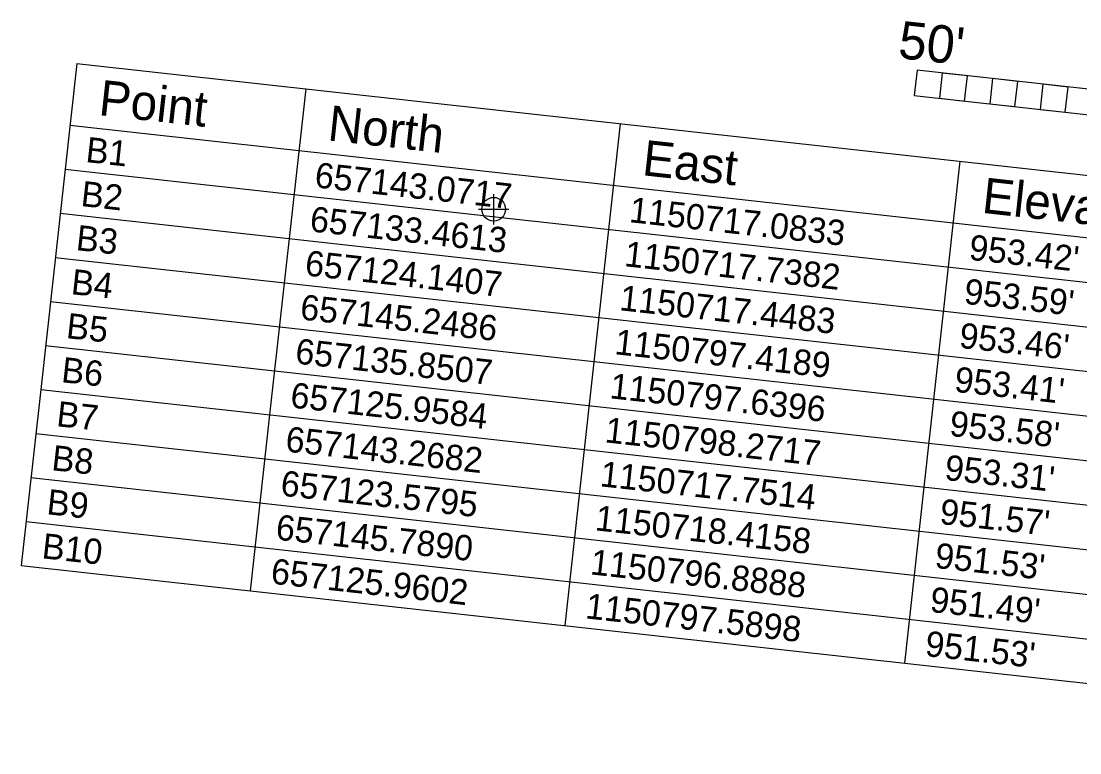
# Model space of a CAD drawing. Extents: x 1150279 to 1151282, y 654632 to 657999.
# Drawn here: x 1150700.1 to 1150909.2, y 656828.1 to 656972.6 of the extents above; entities that cross this region are included whole.
import ezdxf

# ---------------------------------------------------------------- set-up
doc = ezdxf.new("R2010")
doc.units = 0
for name, color, linetype in [('Cogo Default Point CELL', 7, 'Continuous'), ('CTL Sheet Datum Description CELL', 7, 'Continuous'), ('Exist Other Culture Located Object Text', 7, 'Continuous')]:
    doc.layers.add(name, color=color, linetype=linetype)

msp = doc.modelspace()

# ---------------------------------------------------------------- linework, layer by layer
at = {"layer": 'Cogo Default Point CELL'}
for points in [[(1150793.42, 656938.45), (1150793.42, 656935.45)], [(1150790.42, 656935.45), (1150793.42, 656935.45)], [(1150793.42, 656935.45), (1150796.42, 656935.45)], [(1150793.42, 656935.45), (1150793.42, 656932.45)]]:
    msp.add_lwpolyline(points, dxfattribs=at)
msp.add_circle((1150793.42, 656935.45), 2.34, dxfattribs=at)
at = {"layer": 'CTL Sheet Datum Description CELL'}
for points in [[(1150876.48, 656957.93), (1151025.57, 656941.43), (1151026.12, 656946.4), (1150877.03, 656962.9)], [(1150881.45, 656957.38), (1150886.42, 656956.83), (1150886.97, 656961.8), (1150882, 656962.35)], [(1150891.39, 656956.28), (1150896.36, 656955.73), (1150896.91, 656960.7), (1150891.94, 656961.25)], [(1150901.33, 656955.18), (1150906.3, 656954.63), (1150906.85, 656959.6), (1150901.88, 656960.15)]]:
    msp.add_lwpolyline(points, close=True, dxfattribs=at)
at = {"layer": 'Exist Other Culture Located Object Text'}
for p, q in [((1150711.08, 656964.22), (1150703.96, 656899.86)), ((1150711.08, 656964.22), (1151045.54, 656927.21)), ((1150756.3, 656959.21), (1150749.18, 656894.86)), ((1150709.73, 656952.04), (1151044.19, 656915.04)), ((1150818.42, 656952.34), (1150811.3, 656887.98)), ((1150885.51, 656944.92), (1150878.39, 656880.56)), ((1150708.77, 656943.34), (1151043.23, 656906.34)), ((1150708.77, 656943.34), (1151043.23, 656906.34)), ((1150708.77, 656943.34), (1151043.23, 656906.34)), ((1150708.77, 656943.34), (1151043.23, 656906.34)), ((1150708.77, 656943.34), (1151043.23, 656906.34)), ((1150707.8, 656934.65), (1151042.26, 656897.64)), ((1150707.8, 656934.65), (1151042.26, 656897.64)), ((1150707.8, 656934.65), (1151042.26, 656897.64)), ((1150707.8, 656934.65), (1151042.26, 656897.64)), ((1150707.8, 656934.65), (1151042.26, 656897.64)), ((1150706.84, 656925.95), (1151041.3, 656888.95)), ((1150706.84, 656925.95), (1151041.3, 656888.95)), ((1150706.84, 656925.95), (1151041.3, 656888.95)), ((1150706.84, 656925.95), (1151041.3, 656888.95)), ((1150706.84, 656925.95), (1151041.3, 656888.95)), ((1150705.88, 656917.25), (1151040.34, 656880.25)), ((1150705.88, 656917.25), (1151040.34, 656880.25)), ((1150705.88, 656917.25), (1151040.34, 656880.25)), ((1150705.88, 656917.25), (1151040.34, 656880.25)), ((1150705.88, 656917.25), (1151040.34, 656880.25)), ((1150704.92, 656908.56), (1151039.38, 656871.55)), ((1150704.92, 656908.56), (1151039.38, 656871.55)), ((1150704.92, 656908.56), (1151039.38, 656871.55)), ((1150704.92, 656908.56), (1151039.38, 656871.55)), ((1150704.92, 656908.56), (1151039.38, 656871.55)), ((1150703.96, 656899.86), (1150700.11, 656865.07)), ((1150703.96, 656899.86), (1151038.42, 656862.86)), ((1150703.96, 656899.86), (1151038.42, 656862.86)), ((1150703.96, 656899.86), (1151038.42, 656862.86)), ((1150703.96, 656899.86), (1151038.42, 656862.86)), ((1150703.96, 656899.86), (1151038.42, 656862.86)), ((1150749.18, 656894.86), (1150745.33, 656860.07)), ((1150702.99, 656891.16), (1151037.45, 656854.16)), ((1150702.99, 656891.16), (1151037.45, 656854.16)), ((1150702.99, 656891.16), (1151037.45, 656854.16)), ((1150702.99, 656891.16), (1151037.45, 656854.16)), ((1150702.99, 656891.16), (1151037.45, 656854.16)), ((1150811.3, 656887.98), (1150807.45, 656853.19)), ((1150702.03, 656882.46), (1151036.49, 656845.46)), ((1150702.03, 656882.46), (1151036.49, 656845.46)), ((1150702.03, 656882.46), (1151036.49, 656845.46)), ((1150702.03, 656882.46), (1151036.49, 656845.46)), ((1150702.03, 656882.46), (1151036.49, 656845.46)), ((1150878.39, 656880.56), (1150874.54, 656845.77)), ((1150701.07, 656873.77), (1151035.53, 656836.76)), ((1150701.07, 656873.77), (1151035.53, 656836.76)), ((1150701.07, 656873.77), (1151035.53, 656836.76)), ((1150701.07, 656873.77), (1151035.53, 656836.76)), ((1150701.07, 656873.77), (1151035.53, 656836.76)), ((1150700.11, 656865.07), (1151034.57, 656828.07)), ((1150700.11, 656865.07), (1151034.57, 656828.07)), ((1150700.11, 656865.07), (1151034.57, 656828.07)), ((1150700.11, 656865.07), (1151034.57, 656828.07)), ((1150700.11, 656865.07), (1151034.57, 656828.07))]:
    msp.add_line(p, q, dxfattribs=at)

# ---------------------------------------------------------------- texts
at = {"layer": 'CTL Sheet Datum Description CELL'}
msp.add_text("50'", height=7.4, rotation=353.6867, dxfattribs=at).set_placement((1150873.12, 656965.34))
at = {"layer": 'Exist Other Culture Located Object Text'}
for s, height, p in [('Point', 7, (1150715.24, 656954.07)), ('North', 7, (1150760.46, 656949.07)), ('B1', 5, (1150712.7, 656944.79)), ('East', 7, (1150822.58, 656942.2)), ('657143.0717', 5, (1150757.92, 656939.79)), ('B2', 5, (1150711.74, 656936.1)), ('Elevation', 7, (1150889.67, 656934.77)), ('1150717.0833', 5, (1150820.05, 656932.92)), ('657133.4613', 5, (1150756.96, 656931.09)), ('B3', 5, (1150710.78, 656927.4)), ("953.42'", 5, (1150887.14, 656925.5)), ('1150717.7382', 5, (1150819.08, 656924.22)), ('657124.1407', 5, (1150756, 656922.4)), ('B4', 5, (1150709.81, 656918.7)), ('1150717.4483', 5, (1150818.12, 656915.52)), ("953.59'", 5, (1150886.17, 656916.8)), ('657145.2486', 5, (1150755.04, 656913.7)), ('B5', 5, (1150708.85, 656910.01)), ('1150797.4189', 5, (1150817.16, 656906.83)), ("953.46'", 5, (1150885.21, 656908.1)), ('657135.8507', 5, (1150754.08, 656905)), ('B6', 5, (1150707.89, 656901.31)), ("953.41'", 5, (1150884.25, 656899.41)), ('657125.9584', 5, (1150753.11, 656896.31)), ('1150797.6396', 5, (1150816.2, 656898.13)), ('B7', 5, (1150706.93, 656892.61)), ("953.58'", 5, (1150883.29, 656890.71)), ('1150798.2717', 5, (1150815.23, 656889.43)), ('657143.2682', 5, (1150752.15, 656887.61)), ('B8', 5, (1150705.96, 656883.92)), ("953.31'", 5, (1150882.33, 656882.01)), ('1150717.7514', 5, (1150814.27, 656880.74)), ('657123.5795', 5, (1150751.19, 656878.91)), ('B9', 5, (1150705, 656875.22)), ("951.57'", 5, (1150881.36, 656873.31)), ('1150718.4158', 5, (1150813.31, 656872.04)), ('657145.7890', 5, (1150750.23, 656870.22)), ('B10', 5, (1150704.04, 656866.52)), ('1150796.8888', 5, (1150812.35, 656863.34)), ("951.53'", 5, (1150880.4, 656864.62)), ('657125.9602', 5, (1150749.26, 656861.52)), ('1150797.5898', 5, (1150811.39, 656854.65)), ("951.49'", 5, (1150879.44, 656855.92)), ("951.53'", 5, (1150878.48, 656847.22))]:
    msp.add_text(s, height=height, rotation=353.6867, dxfattribs=at).set_placement(p)

doc.saveas('drawing.dxf')
